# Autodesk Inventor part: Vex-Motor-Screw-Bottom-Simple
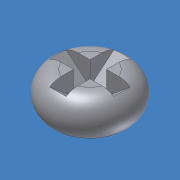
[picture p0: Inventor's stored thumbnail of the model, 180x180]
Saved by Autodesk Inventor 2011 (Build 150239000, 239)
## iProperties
Created: 2007-08
Part Number: Vex-Motor-Screw-Bottom-Simple
Material: Steel
Document SubType Name: Modeling
Density: 7.85 g/cm^3
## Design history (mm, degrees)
feature "Base1"
body "Solid1"
